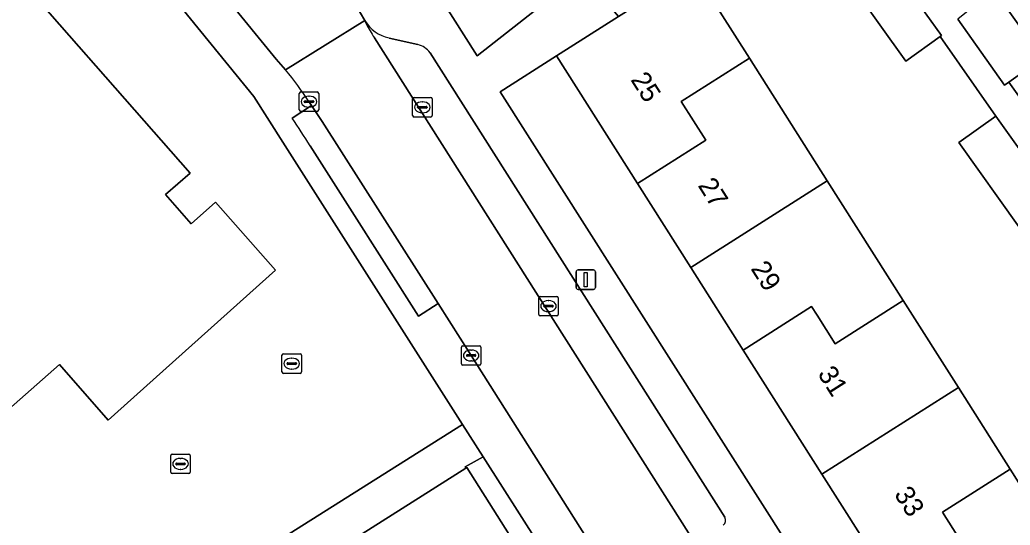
# Model space of a CAD drawing. Extents: x 162344 to 162869, y 381217 to 381818.
# Drawn here: x 162459.1 to 162509.9, y 381626.8 to 381652.8 of the extents above; entities that cross this region are included whole.
import ezdxf

# ---------------------------------------------------------------- set-up
doc = ezdxf.new("R2010")
doc.units = 0
for name, color, linetype in [('IMGEO_Erf', 7, 'Continuous'), ('IMGEO_Groenvoorziening', 7, 'Continuous'), ('IMGEO_Kolk', 7, 'Continuous'), ('IMGEO_Lichtmast', 7, 'Continuous'), ('IMGEO_Pand', 7, 'Continuous'), ('IMGEO_Pand_nummerreeks', 7, 'Continuous'), ('IMGEO_Parkeervlak_open', 7, 'Continuous'), ('IMGEO_Rijbaan_lokaal_open', 7, 'Continuous'), ('IMGEO_Voetpad_open', 7, 'Continuous')]:
    doc.layers.add(name, color=color, linetype=linetype)

msp = doc.modelspace()

# ---------------------------------------------------------------- linework, layer by layer
at = {"layer": 'IMGEO_Erf'}
for points in [[(162481.795, 381631.988), (162472.56, 381646.493), (162471.067, 381648.837), (162460.935, 381661.289), (162452.016, 381672.565), (162451.197, 381672.343), (162448.302, 381667.139), (162445.27, 381668.731), (162442.545, 381663.577), (162439.544, 381661.021), (162435.222, 381659.331), (162436.115, 381656.689), (162431.972, 381654.923), (162432.233, 381653.635), (162452.631, 381613.197), (162453.177, 381613.49), (162453.166, 381613.535), (162453.909, 381613.922), (162459.405, 381616.959), (162465.658, 381620.415), (162465.1, 381621.456)], [(162457.002, 381631.47), (162440.439, 381650.319), (162443.233, 381652.774), (162442.142, 381654.015), (162449.248, 381660.259), (162450.273, 381659.093), (162453.049, 381661.533), (162455.031, 381659.277), (162457.216, 381661.198), (162459.336, 381658.786), (162457.226, 381656.932), (162467.795, 381644.904), (162466.539, 381643.799), (162467.852, 381642.305), (162469.109, 381643.41), (162472.178, 381639.917), (162463.598, 381632.222), (162461.097, 381635.067)], [(162509.729, 381614.501), (162506.891, 381618.974), (162504.179, 381623.249), (162500.254, 381629.436), (162496.21, 381635.81), (162493.518, 381640.054), (162490.785, 381644.361), (162486.625, 381650.919), (162483.717, 381649.074), (162500, 381623.471), (162531.035, 381574.671), (162533.863, 381576.458), (162531.166, 381580.71), (162527.169, 381587.01), (162523.206, 381593.256), (162520.428, 381597.636), (162517.63, 381602.045), (162513.719, 381608.21)], [(162500, 381603.428), (162482.857, 381630.326), (162481.918, 381629.814), (162481.958, 381629.752), (162482.007, 381629.783), (162485.338, 381624.533), (162488.628, 381619.345), (162491.92, 381614.157), (162495.211, 381608.969), (162498.502, 381603.78), (162501.793, 381598.593), (162505.084, 381593.404), (162508.375, 381588.216), (162511.667, 381583.028), (162514.958, 381577.839), (162518.25, 381572.651), (162521.79, 381567.07), (162522.773, 381567.696), (162522.094, 381568.761)]]:
    msp.add_lwpolyline(points, close=True, dxfattribs=at)
for points in [[(162510.099, 381663.114), (162506.026, 381668.154), (162499.933, 381663.224), (162500.114, 381662.996), (162501.945, 381664.309), (162504.599, 381660.606), (162502.768, 381659.294), (162504.496, 381657.227), (162506.17, 381658.416), (162509.083, 381654.315), (162511.58, 381650.8), (162509.855, 381649.575), (162511.736, 381646.935)], [(162510.377, 381642.133), (162507.288, 381646.468), (162509.19, 381647.823), (162506.326, 381651.913), (162504.565, 381650.654), (162501.976, 381654.276), (162499.167, 381658.207), (162500.996, 381659.515), (162499.313, 381661.868), (162488.804, 381654.132), (162489.805, 381652.936), (162493.635, 381655.366), (162496.526, 381650.81), (162500.523, 381644.51), (162504.431, 381638.351), (162507.26, 381633.892), (162509.92, 381629.7), (162513.898, 381623.43)]]:
    msp.add_lwpolyline(points, dxfattribs=at)
at = {"layer": 'IMGEO_Groenvoorziening'}
msp.add_lwpolyline([(162483.97, 381660.263), (162479.032, 381656.467), (162482.537, 381650.933), (162487.93, 381655.177)], close=True, dxfattribs=at)
at = {"layer": 'IMGEO_Kolk'}
for p, q in [((162473.403, 381648.145), (162473.403, 381648.997)), ((162473.478, 381649.071), (162474.33, 381649.071)), ((162473.891, 381648.851), (162473.916, 381648.851)), ((162474.404, 381648.997), (162474.404, 381648.145)), ((162479.227, 381647.856), (162479.227, 381648.708)), ((162479.302, 381648.782), (162480.154, 381648.782)), ((162480.228, 381648.708), (162480.228, 381647.856)), ((162473.662, 381648.565), (162473.662, 381648.577)), ((162474.1, 381648.528), (162473.702, 381648.528)), ((162473.705, 381648.614), (162474.103, 381648.614)), ((162473.914, 381648.291), (162473.889, 381648.291)), ((162474.146, 381648.577), (162474.146, 381648.565)), ((162479.486, 381648.276), (162479.486, 381648.288)), ((162479.924, 381648.239), (162479.526, 381648.239)), ((162479.529, 381648.325), (162479.927, 381648.325)), ((162479.715, 381648.562), (162479.74, 381648.562)), ((162479.97, 381648.288), (162479.97, 381648.276)), ((162474.33, 381648.071), (162473.478, 381648.071)), ((162480.154, 381647.782), (162479.302, 381647.782)), ((162479.738, 381648.002), (162479.713, 381648.002)), ((162485.705, 381637.646), (162485.705, 381638.498)), ((162485.78, 381638.572), (162486.632, 381638.572)), ((162486.706, 381638.498), (162486.706, 381637.646)), ((162485.964, 381638.066), (162485.964, 381638.078)), ((162486.402, 381638.029), (162486.004, 381638.029)), ((162486.007, 381638.115), (162486.405, 381638.115)), ((162486.193, 381638.352), (162486.218, 381638.352)), ((162486.448, 381638.078), (162486.448, 381638.066)), ((162486.632, 381637.572), (162485.78, 381637.572)), ((162486.216, 381637.792), (162486.191, 381637.792)), ((162481.734, 381635.11), (162481.734, 381635.962)), ((162481.809, 381636.036), (162482.661, 381636.036)), ((162482.735, 381635.962), (162482.735, 381635.11)), ((162472.517, 381634.692), (162472.517, 381635.544)), ((162472.592, 381635.618), (162473.444, 381635.618)), ((162473.005, 381635.398), (162473.03, 381635.398)), ((162473.518, 381635.544), (162473.518, 381634.692)), ((162481.993, 381635.53), (162481.993, 381635.542)), ((162482.431, 381635.493), (162482.033, 381635.493)), ((162482.036, 381635.579), (162482.434, 381635.579)), ((162482.222, 381635.816), (162482.247, 381635.816)), ((162482.477, 381635.542), (162482.477, 381635.53)), ((162472.776, 381635.112), (162472.776, 381635.124)), ((162473.214, 381635.075), (162472.816, 381635.075)), ((162472.819, 381635.161), (162473.217, 381635.161)), ((162473.26, 381635.124), (162473.26, 381635.112)), ((162482.661, 381635.036), (162481.809, 381635.036)), ((162482.245, 381635.256), (162482.22, 381635.256)), ((162473.444, 381634.618), (162472.592, 381634.618)), ((162473.028, 381634.838), (162473.003, 381634.838)), ((162466.806, 381629.542), (162466.806, 381630.394)), ((162466.881, 381630.468), (162467.733, 381630.468)), ((162467.807, 381630.394), (162467.807, 381629.542)), ((162467.065, 381629.962), (162467.065, 381629.974)), ((162467.503, 381629.925), (162467.105, 381629.925)), ((162467.108, 381630.011), (162467.506, 381630.011)), ((162467.294, 381630.248), (162467.319, 381630.248)), ((162467.549, 381629.974), (162467.549, 381629.962)), ((162467.733, 381629.468), (162466.881, 381629.468)), ((162467.317, 381629.688), (162467.292, 381629.688))]:
    msp.add_line(p, q, dxfattribs=at)
for points in [[(162473.403, 381648.145), (162473.403, 381648.997)], [(162473.478, 381649.071), (162474.33, 381649.071)], [(162474.404, 381648.997), (162474.404, 381648.145)], [(162479.227, 381647.856), (162479.227, 381648.708)], [(162479.302, 381648.782), (162480.154, 381648.782)], [(162480.228, 381648.708), (162480.228, 381647.856)], [(162474.33, 381648.071), (162473.478, 381648.071)], [(162480.154, 381647.782), (162479.302, 381647.782)], [(162485.705, 381637.646), (162485.705, 381638.498)], [(162485.78, 381638.572), (162486.632, 381638.572)], [(162486.706, 381638.498), (162486.706, 381637.646)], [(162486.632, 381637.572), (162485.78, 381637.572)], [(162481.734, 381635.11), (162481.734, 381635.962)], [(162481.809, 381636.036), (162482.661, 381636.036)], [(162482.735, 381635.962), (162482.735, 381635.11)], [(162472.517, 381634.692), (162472.517, 381635.544)], [(162472.592, 381635.618), (162473.444, 381635.618)], [(162473.518, 381635.544), (162473.518, 381634.692)], [(162482.661, 381635.036), (162481.809, 381635.036)], [(162473.444, 381634.618), (162472.592, 381634.618)], [(162466.806, 381629.542), (162466.806, 381630.394)], [(162466.881, 381630.468), (162467.733, 381630.468)], [(162467.807, 381630.394), (162467.807, 381629.542)], [(162467.733, 381629.468), (162466.881, 381629.468)]]:
    msp.add_lwpolyline(points, dxfattribs=at)
for centre, radius, start, end in [((162473.48, 381648.995), 0.0765, 91.552, 178.448), ((162473.48, 381648.995), 0.0765, 91.552, 178.448), ((162474.328, 381648.995), 0.0765, 1.552, 88.448), ((162474.328, 381648.995), 0.0765, 1.552, 88.448), ((162479.304, 381648.706), 0.0765, 91.552, 178.448), ((162479.304, 381648.706), 0.0765, 91.552, 178.448), ((162480.152, 381648.706), 0.0765, 1.552, 88.448), ((162480.152, 381648.706), 0.0765, 1.552, 88.448), ((162473.48, 381648.147), 0.0765, 181.552, 268.448), ((162473.48, 381648.147), 0.0765, 181.552, 268.448), ((162473.702, 381648.574), 0.0403, 85.8775, 175.7526), ((162473.699, 381648.564), 0.0366, 178.938, 274.7102), ((162474.103, 381648.571), 0.043, 264.8664, 352.4533), ((162474.107, 381648.576), 0.0386, 1.7309, 96.639), ((162474.328, 381648.147), 0.0765, 271.552, 358.448), ((162474.328, 381648.147), 0.0765, 271.552, 358.448), ((162479.526, 381648.285), 0.0403, 85.8775, 175.7526), ((162479.523, 381648.275), 0.0366, 178.938, 274.7102), ((162479.927, 381648.282), 0.043, 264.8664, 352.4533), ((162479.931, 381648.287), 0.0386, 1.7309, 96.639), ((162479.304, 381647.858), 0.0765, 181.552, 268.448), ((162479.304, 381647.858), 0.0765, 181.552, 268.448), ((162480.152, 381647.858), 0.0765, 271.552, 358.448), ((162480.152, 381647.858), 0.0765, 271.552, 358.448), ((162485.782, 381638.496), 0.0765, 91.552, 178.448), ((162485.782, 381638.496), 0.0765, 91.552, 178.448), ((162486.63, 381638.496), 0.0765, 1.552, 88.448), ((162486.63, 381638.496), 0.0765, 1.552, 88.448), ((162486.004, 381638.075), 0.0403, 85.8775, 175.7526), ((162486.001, 381638.065), 0.0366, 178.938, 274.7102), ((162486.405, 381638.072), 0.043, 264.8664, 352.4533), ((162486.409, 381638.077), 0.0386, 1.7309, 96.639), ((162485.782, 381637.648), 0.0765, 181.552, 268.448), ((162485.782, 381637.648), 0.0765, 181.552, 268.448), ((162486.63, 381637.648), 0.0765, 271.552, 358.448), ((162486.63, 381637.648), 0.0765, 271.552, 358.448), ((162481.811, 381635.96), 0.0765, 91.552, 178.448), ((162481.811, 381635.96), 0.0765, 91.552, 178.448), ((162482.659, 381635.96), 0.0765, 1.552, 88.448), ((162482.659, 381635.96), 0.0765, 1.552, 88.448), ((162472.594, 381635.542), 0.0765, 91.552, 178.448), ((162472.594, 381635.542), 0.0765, 91.552, 178.448), ((162473.442, 381635.542), 0.0765, 1.552, 88.448), ((162473.442, 381635.542), 0.0765, 1.552, 88.448), ((162482.033, 381635.539), 0.0403, 85.8775, 175.7526), ((162482.03, 381635.529), 0.0366, 178.938, 274.7102), ((162482.434, 381635.536), 0.043, 264.8664, 352.4533), ((162482.438, 381635.541), 0.0386, 1.7309, 96.639), ((162472.816, 381635.121), 0.0403, 85.8775, 175.7526), ((162472.813, 381635.111), 0.0366, 178.938, 274.7102), ((162473.217, 381635.118), 0.043, 264.8664, 352.4533), ((162473.221, 381635.123), 0.0386, 1.7309, 96.639), ((162481.811, 381635.112), 0.0765, 181.552, 268.448), ((162481.811, 381635.112), 0.0765, 181.552, 268.448), ((162482.659, 381635.112), 0.0765, 271.552, 358.448), ((162482.659, 381635.112), 0.0765, 271.552, 358.448), ((162472.594, 381634.694), 0.0765, 181.552, 268.448), ((162472.594, 381634.694), 0.0765, 181.552, 268.448), ((162473.442, 381634.694), 0.0765, 271.552, 358.448), ((162473.442, 381634.694), 0.0765, 271.552, 358.448), ((162466.883, 381630.392), 0.0765, 91.552, 178.448), ((162466.883, 381630.392), 0.0765, 91.552, 178.448), ((162467.731, 381630.392), 0.0765, 1.552, 88.448), ((162467.731, 381630.392), 0.0765, 1.552, 88.448), ((162467.105, 381629.971), 0.0403, 85.8775, 175.7526), ((162467.102, 381629.961), 0.0366, 178.938, 274.7102), ((162467.506, 381629.968), 0.043, 264.8664, 352.4533), ((162467.51, 381629.973), 0.0386, 1.7309, 96.639), ((162466.883, 381629.544), 0.0765, 181.552, 268.448), ((162466.883, 381629.544), 0.0765, 181.552, 268.448), ((162467.731, 381629.544), 0.0765, 271.552, 358.448), ((162467.731, 381629.544), 0.0765, 271.552, 358.448)]:
    msp.add_arc(centre, radius, start, end, dxfattribs=at)
for centre, major_axis, ratio, start_param, end_param in [((162473.89, 381648.571), (-0.387, 0.002), 0.722429, 4.712389, 7.853982), ((162473.915, 381648.571), (-0.39, 0.002), 0.717154, 1.570796, 4.712389), ((162479.714, 381648.282), (-0.387, 0.002), 0.722429, 4.712389, 7.853982), ((162479.739, 381648.282), (-0.39, 0.002), 0.717154, 1.570796, 4.712389), ((162486.192, 381638.072), (-0.387, 0.002), 0.722429, 4.712389, 7.853982), ((162486.217, 381638.072), (-0.39, 0.002), 0.717154, 1.570796, 4.712389), ((162473.004, 381635.118), (-0.387, 0.002), 0.722429, 4.712389, 7.853982), ((162473.029, 381635.118), (-0.39, 0.002), 0.717154, 1.570796, 4.712389), ((162482.221, 381635.536), (-0.387, 0.002), 0.722429, 4.712389, 7.853982), ((162482.246, 381635.536), (-0.39, 0.002), 0.717154, 1.570796, 4.712389), ((162467.293, 381629.968), (-0.387, 0.002), 0.722429, 4.712389, 7.853982), ((162467.318, 381629.968), (-0.39, 0.002), 0.717154, 1.570796, 4.712389)]:
    msp.add_ellipse(centre, major_axis=major_axis, ratio=ratio, start_param=start_param, end_param=end_param, dxfattribs=at)
at = {"layer": 'IMGEO_Lichtmast'}
for p, q in [((162487.626, 381639.03), (162487.626, 381639.83)), ((162487.626, 381639.83), (162487.626, 381639.03)), ((162487.726, 381639.93), (162488.516, 381639.93)), ((162488.516, 381639.93), (162487.726, 381639.93)), ((162488.616, 381639.83), (162488.616, 381639.03)), ((162488.616, 381639.03), (162488.616, 381639.83)), ((162488.516, 381638.93), (162487.726, 381638.93)), ((162487.726, 381638.93), (162488.516, 381638.93))]:
    msp.add_line(p, q, dxfattribs=at)
msp.add_lwpolyline([(162488.046, 381639.805), (162488.196, 381639.805), (162488.196, 381639.055), (162488.046, 381639.055), (162488.046, 381639.805)], dxfattribs=at)
for centre, start, end in [((162487.726, 381639.83), 90, 180), ((162487.726, 381639.83), 90, 180), ((162488.516, 381639.83), 0, 90), ((162488.516, 381639.83), 360, 90), ((162487.726, 381639.03), 180, 270), ((162487.726, 381639.03), 180, 270), ((162488.516, 381639.03), 270, 0), ((162488.516, 381639.03), 270, 0)]:
    msp.add_arc(centre, 0.1, start, end, dxfattribs=at)
at = {"layer": 'IMGEO_Pand'}
for points in [[(162461.097, 381635.067), (162463.598, 381632.222), (162472.178, 381639.917), (162469.109, 381643.41), (162467.852, 381642.305), (162466.539, 381643.799), (162467.795, 381644.904), (162457.226, 381656.932), (162459.336, 381658.786), (162457.216, 381661.198), (162455.031, 381659.277), (162453.049, 381661.533), (162450.273, 381659.093), (162449.248, 381660.259), (162442.142, 381654.015), (162443.233, 381652.774), (162440.439, 381650.319), (162457.002, 381631.47)], [(162496.526, 381650.81), (162493.635, 381655.366), (162489.805, 381652.936), (162486.625, 381650.919), (162490.785, 381644.361), (162494.289, 381646.589), (162493.022, 381648.583)], [(162503.877, 381655.484), (162501.976, 381654.276), (162504.565, 381650.654), (162506.326, 381651.913), (162506.394, 381651.962)], [(162509.083, 381654.315), (162507.227, 381652.808), (162509.634, 381649.418), (162509.855, 381649.575), (162511.58, 381650.8)], [(162496.526, 381650.81), (162493.022, 381648.583), (162494.289, 381646.589), (162490.785, 381644.361), (162493.518, 381640.054), (162500, 381644.177), (162500.523, 381644.51)], [(162509.19, 381647.823), (162507.288, 381646.468), (162510.377, 381642.133), (162512.349, 381643.387)], [(162500.523, 381644.51), (162500, 381644.177), (162493.518, 381640.054), (162496.21, 381635.81), (162499.723, 381638.044), (162500, 381637.608), (162500.939, 381636.131), (162504.431, 381638.351)], [(162504.431, 381638.351), (162500.939, 381636.131), (162500, 381637.608), (162499.723, 381638.044), (162496.21, 381635.81), (162500.254, 381629.436), (162507.26, 381633.892)], [(162509.92, 381629.7), (162507.26, 381633.892), (162500.254, 381629.436), (162504.179, 381623.249), (162507.708, 381625.494), (162506.441, 381627.488)], [(162482.007, 381629.783), (162481.958, 381629.752), (162474.912, 381625.272), (162475.104, 381624.97), (162472.535, 381623.344), (162475.66, 381618.407), (162478.233, 381620.036), (162485.338, 381624.533)], [(162509.92, 381629.7), (162506.441, 381627.488), (162507.708, 381625.494), (162504.179, 381623.249), (162506.891, 381618.974), (162513.898, 381623.43)]]:
    msp.add_lwpolyline(points, close=True, dxfattribs=at)
at = {"layer": 'IMGEO_Parkeervlak_open'}
for points in [[(162476.776, 381652.741), (162476.853, 381652.559)], [(162477.262, 381651.857), (162493.957, 381625.539)], [(162479.495, 381651.505), (162478.015, 381651.84)], [(162495.26, 381627.225), (162480.123, 381651.083)]]:
    msp.add_lwpolyline(points, dxfattribs=at)
for centre, radius, start, end in [((162478.409, 381653.685), 1.886, 210.0177, 257.9331), ((162485.105, 381656.897), 9.323, 207.7286, 212.7234), ((162479.197, 381650.383), 1.161, 37.0908, 75.109), ((162495.005, 381627.065), 0.301, 305.7366, 32.1882)]:
    msp.add_arc(centre, radius, start, end, dxfattribs=at)
at = {"layer": 'IMGEO_Rijbaan_lokaal_open'}
for points in [[(162465.255, 381666.596), (162464.699, 381667.264), (162461.143, 381664.345), (162464.301, 381660.45), (162472.225, 381650.761), (162472.704, 381650.202), (162476.776, 381652.741), (162476.558, 381653.122), (162475.793, 381654.37)], [(162476.853, 381652.559), (162476.776, 381652.741), (162472.704, 381650.202)], [(162473.904, 381648.571), (162474.039, 381648.375), (162474.586, 381647.556), (162480.538, 381638.212), (162482.235, 381635.536), (162491.687, 381620.613), (162500.464, 381606.783), (162502.811, 381603.082), (162506.636, 381605.528), (162506.577, 381605.621), (162506.536, 381605.712), (162494.37, 381624.906), (162494.322, 381624.959), (162493.957, 381625.539), (162477.262, 381651.857)]]:
    msp.add_lwpolyline(points, dxfattribs=at)
for centre, radius, start, end in [((162485.105, 381656.897), 9.323, 207.7286, 212.7234), ((162458.425, 381638.439), 18.5, 33.2064, 39.4807)]:
    msp.add_arc(centre, radius, start, end, dxfattribs=at)
at = {"layer": 'IMGEO_Voetpad_open'}
for points in [[(162472.704, 381650.202), (162472.225, 381650.761), (162464.301, 381660.45), (162461.143, 381664.345), (162453.433, 381673.852), (162452.016, 381672.565), (162460.935, 381661.289), (162471.067, 381648.837), (162472.56, 381646.493), (162481.795, 381631.988), (162482.857, 381630.326), (162500, 381603.428), (162522.094, 381568.761), (162522.773, 381567.696), (162523.584, 381566.423), (162523.028, 381566.054), (162525.538, 381562.087), (162528.355, 381557.526), (162532.073, 381550.22), (162532.638, 381549.091), (162533.893, 381543.857)], [(162536.254, 381572.675), (162534.661, 381575.207), (162533.863, 381576.458), (162531.035, 381574.671), (162500, 381623.471), (162483.717, 381649.074), (162486.625, 381650.919), (162489.805, 381652.936), (162488.804, 381654.132), (162487.93, 381655.177), (162482.537, 381650.933), (162479.032, 381656.467), (162483.97, 381660.263), (162483.121, 381661.563), (162478.205, 381657.739), (162476.197, 381660.891)], [(162503.877, 381655.484), (162506.394, 381651.962), (162506.326, 381651.913), (162509.19, 381647.823), (162512.349, 381643.387)], [(162475.793, 381654.37), (162476.558, 381653.122), (162476.776, 381652.741)], [(162511.736, 381646.935), (162509.855, 381649.575), (162509.634, 381649.418), (162507.227, 381652.808)], [(162478.015, 381651.84), (162479.495, 381651.505)], [(162480.123, 381651.083), (162495.26, 381627.225)], [(162473.037, 381647.719), (162474.039, 381648.375), (162473.904, 381648.571)], [(162474.586, 381647.556), (162474.039, 381648.375), (162473.037, 381647.719)], [(162473.959, 381646.306), (162475.997, 381643.106), (162479.529, 381637.56), (162480.538, 381638.212), (162474.586, 381647.556)], [(162536.173, 381550.404), (162533.548, 381554.605), (162528.482, 381562.594), (162519.683, 381576.506), (162509.771, 381592.107), (162504.221, 381600.859), (162502.811, 381603.082), (162500.464, 381606.783), (162491.687, 381620.613), (162482.235, 381635.536), (162480.538, 381638.212), (162479.529, 381637.56), (162475.997, 381643.106), (162473.959, 381646.306)], [(162465.983, 381618.274), (162467.97, 381619.402), (162468.147, 381619.499), (162469.201, 381620.077), (162468.584, 381621.093), (162470.747, 381622.562), (162474.912, 381625.272), (162481.958, 381629.752), (162481.918, 381629.814), (162482.857, 381630.326), (162481.795, 381631.988), (162465.1, 381621.456), (162465.658, 381620.415), (162459.405, 381616.959), (162453.909, 381613.922)]]:
    msp.add_lwpolyline(points, dxfattribs=at)
for centre, radius, start, end in [((162478.409, 381653.685), 1.886, 210.0177, 257.9331), ((162479.197, 381650.383), 1.161, 37.0908, 75.109), ((162458.425, 381638.439), 18.5, 33.2064, 39.4807), ((162447.584, 381630.103), 30.954, 31.5633, 34.6866), ((162447.584, 381630.103), 30.954, 31.5633, 34.6866), ((162495.005, 381627.065), 0.301, 305.7366, 32.1882)]:
    msp.add_arc(centre, radius, start, end, dxfattribs=at)

# ---------------------------------------------------------------- texts
at = {"layer": 'IMGEO_Pand_nummerreeks'}
for s, p in [('25', (162490.398, 381649.697)), ('27', (162493.851, 381644.267)), ('29', (162496.568, 381639.994)), ('31', (162500.002, 381634.594)), ('33', (162503.932, 381628.413))]:
    msp.add_text(s, height=1, rotation=302.4521, dxfattribs=at).set_placement(p)

doc.saveas('drawing.dxf')
